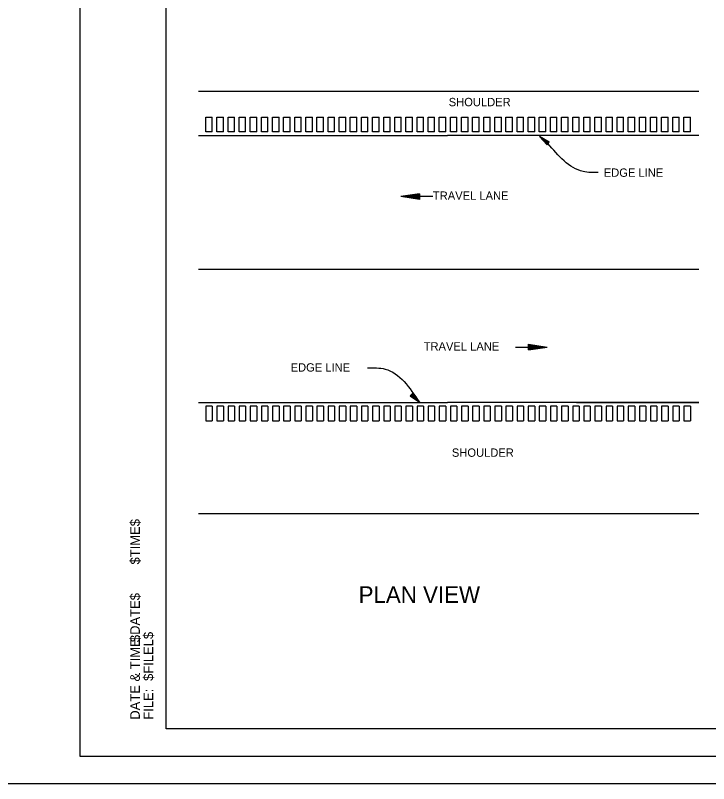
# Model space of a CAD drawing. Extents: x 3575 to 11445, y 9479 to 13278.
# Drawn here: x 7536 to 8035, y 10000 to 10553 of the extents above; entities that cross this region are included whole.
import ezdxf

# ---------------------------------------------------------------- set-up
doc = ezdxf.new("R2010")
doc.units = 0
for name, color, linetype in [('Default', 7, 'Continuous'), ('R_NoPlot', 7, 'Continuous'), ('STAMP_PRELIMINARY', 7, 'Continuous')]:
    doc.layers.add(name, color=color, linetype=linetype)

msp = doc.modelspace()

# ---------------------------------------------------------------- linework, layer by layer
at = {"layer": 'Default'}
for p, q in [((7667.92, 10498.47), (8027.8, 10498.47)), ((7673.12, 10469.13), (7673.12, 10479.77)), ((7673.12, 10479.77), (7677.8, 10479.77)), ((7677.8, 10469.13), (7677.8, 10479.77)), ((7681.12, 10469.13), (7681.12, 10479.77)), ((7681.12, 10479.77), (7685.8, 10479.77)), ((7685.8, 10469.13), (7685.8, 10479.77)), ((7689.12, 10469.13), (7689.12, 10479.77)), ((7689.12, 10479.77), (7693.8, 10479.77)), ((7693.8, 10469.13), (7693.8, 10479.77)), ((7697.12, 10469.13), (7697.12, 10479.77)), ((7697.12, 10479.77), (7701.8, 10479.77)), ((7701.8, 10469.13), (7701.8, 10479.77)), ((7705.12, 10469.13), (7705.12, 10479.77)), ((7705.12, 10479.77), (7709.8, 10479.77)), ((7709.8, 10469.13), (7709.8, 10479.77)), ((7713.12, 10469.13), (7713.12, 10479.77)), ((7713.12, 10479.77), (7717.8, 10479.77)), ((7717.8, 10469.13), (7717.8, 10479.77)), ((7721.12, 10469.13), (7721.12, 10479.77)), ((7721.12, 10479.77), (7725.8, 10479.77)), ((7725.8, 10469.13), (7725.8, 10479.77)), ((7729.12, 10469.13), (7729.12, 10479.77)), ((7729.12, 10479.77), (7733.8, 10479.77)), ((7733.8, 10469.13), (7733.8, 10479.77)), ((7737.12, 10469.13), (7737.12, 10479.77)), ((7737.12, 10479.77), (7741.8, 10479.77)), ((7741.8, 10469.13), (7741.8, 10479.77)), ((7745.12, 10469.13), (7745.12, 10479.77)), ((7745.12, 10479.77), (7749.8, 10479.77)), ((7749.8, 10469.13), (7749.8, 10479.77)), ((7753.12, 10469.13), (7753.12, 10479.77)), ((7753.12, 10479.77), (7757.8, 10479.77)), ((7757.8, 10469.13), (7757.8, 10479.77)), ((7761.12, 10469.13), (7761.12, 10479.77)), ((7761.12, 10479.77), (7765.8, 10479.77)), ((7765.8, 10469.13), (7765.8, 10479.77)), ((7769.12, 10469.13), (7769.12, 10479.77)), ((7769.12, 10479.77), (7773.8, 10479.77)), ((7773.8, 10469.13), (7773.8, 10479.77)), ((7777.12, 10469.13), (7777.12, 10479.77)), ((7777.12, 10479.77), (7781.8, 10479.77)), ((7781.8, 10469.13), (7781.8, 10479.77)), ((7785.12, 10469.13), (7785.12, 10479.77)), ((7785.12, 10479.77), (7789.8, 10479.77)), ((7789.8, 10469.13), (7789.8, 10479.77)), ((7793.12, 10469.13), (7793.12, 10479.77)), ((7793.12, 10469.13), (7793.12, 10479.77)), ((7793.12, 10479.77), (7797.8, 10479.77)), ((7797.8, 10469.13), (7797.8, 10479.77)), ((7801.12, 10469.13), (7801.12, 10479.77)), ((7801.12, 10479.77), (7805.8, 10479.77)), ((7805.8, 10469.13), (7805.8, 10479.77)), ((7809.12, 10469.13), (7809.12, 10479.77)), ((7809.12, 10479.77), (7813.8, 10479.77)), ((7813.8, 10469.13), (7813.8, 10479.77)), ((7817.12, 10469.13), (7817.12, 10479.77)), ((7817.12, 10479.77), (7821.8, 10479.77)), ((7821.8, 10469.13), (7821.8, 10479.77)), ((7825.12, 10469.13), (7825.12, 10479.77)), ((7825.12, 10479.77), (7829.8, 10479.77)), ((7829.8, 10469.13), (7829.8, 10479.77)), ((7833.12, 10469.13), (7833.12, 10479.77)), ((7833.12, 10479.77), (7837.8, 10479.77)), ((7837.8, 10469.13), (7837.8, 10479.77)), ((7841.12, 10469.13), (7841.12, 10479.77)), ((7841.12, 10479.77), (7845.8, 10479.77)), ((7845.8, 10469.13), (7845.8, 10479.77)), ((7849.12, 10469.13), (7849.12, 10479.77)), ((7849.12, 10479.77), (7853.8, 10479.77)), ((7853.8, 10469.13), (7853.8, 10479.77)), ((7857.12, 10469.13), (7857.12, 10479.77)), ((7857.12, 10479.77), (7861.8, 10479.77)), ((7861.8, 10469.13), (7861.8, 10479.77)), ((7865.12, 10469.13), (7865.12, 10479.77)), ((7865.12, 10479.77), (7869.8, 10479.77)), ((7869.8, 10469.13), (7869.8, 10479.77)), ((7873.12, 10469.13), (7873.12, 10479.77)), ((7873.12, 10479.77), (7877.8, 10479.77)), ((7877.8, 10469.13), (7877.8, 10479.77)), ((7881.12, 10469.13), (7881.12, 10479.77)), ((7881.12, 10479.77), (7885.8, 10479.77)), ((7885.8, 10469.13), (7885.8, 10479.77)), ((7889.12, 10469.13), (7889.12, 10479.77)), ((7889.12, 10479.77), (7893.8, 10479.77)), ((7893.8, 10469.13), (7893.8, 10479.77)), ((7897.12, 10469.13), (7897.12, 10479.77)), ((7897.12, 10479.77), (7901.8, 10479.77)), ((7901.8, 10469.13), (7901.8, 10479.77)), ((7905.12, 10469.13), (7905.12, 10479.77)), ((7905.12, 10479.77), (7909.8, 10479.77)), ((7909.8, 10469.13), (7909.8, 10479.77)), ((7913.12, 10469.13), (7913.12, 10479.77)), ((7913.12, 10479.77), (7917.8, 10479.77)), ((7917.8, 10469.13), (7917.8, 10479.77)), ((7921.12, 10469.13), (7921.12, 10479.77)), ((7921.12, 10479.77), (7925.8, 10479.77)), ((7925.8, 10469.13), (7925.8, 10479.77)), ((7929.12, 10469.13), (7929.12, 10479.77)), ((7929.12, 10479.77), (7933.8, 10479.77)), ((7933.8, 10469.13), (7933.8, 10479.77)), ((7937.12, 10469.13), (7937.12, 10479.77)), ((7937.12, 10479.77), (7941.8, 10479.77)), ((7941.8, 10469.13), (7941.8, 10479.77)), ((7945.12, 10469.13), (7945.12, 10479.77)), ((7945.12, 10479.77), (7949.8, 10479.77)), ((7949.8, 10469.13), (7949.8, 10479.77)), ((7953.12, 10469.13), (7953.12, 10479.77)), ((7953.12, 10479.77), (7957.8, 10479.77)), ((7957.8, 10469.13), (7957.8, 10479.77)), ((7961.12, 10469.13), (7961.12, 10479.77)), ((7961.12, 10479.77), (7965.8, 10479.77)), ((7965.8, 10469.13), (7965.8, 10479.77)), ((7969.12, 10469.13), (7969.12, 10479.77)), ((7969.12, 10479.77), (7973.8, 10479.77)), ((7973.8, 10469.13), (7973.8, 10479.77)), ((7977.12, 10469.13), (7977.12, 10479.77)), ((7977.12, 10479.77), (7981.8, 10479.77)), ((7981.8, 10469.13), (7981.8, 10479.77)), ((7985.12, 10469.13), (7985.12, 10479.77)), ((7985.12, 10479.77), (7989.8, 10479.77)), ((7989.8, 10469.13), (7989.8, 10479.77)), ((7993.12, 10469.13), (7993.12, 10479.77)), ((7993.12, 10479.77), (7997.8, 10479.77)), ((7997.8, 10469.13), (7997.8, 10479.77)), ((8001.12, 10469.13), (8001.12, 10479.77)), ((8001.12, 10479.77), (8005.8, 10479.77)), ((8005.8, 10469.13), (8005.8, 10479.77)), ((8009.12, 10469.13), (8009.12, 10479.77)), ((8009.12, 10479.77), (8013.8, 10479.77)), ((8013.8, 10469.13), (8013.8, 10479.77)), ((8017.12, 10469.13), (8017.12, 10479.77)), ((8017.12, 10479.77), (8021.8, 10479.77)), ((8021.8, 10469.13), (8021.8, 10479.77)), ((7667.92, 10466.47), (7847.02, 10466.47)), ((7677.8, 10469.13), (7673.12, 10469.13)), ((7685.8, 10469.13), (7681.12, 10469.13)), ((7693.8, 10469.13), (7689.12, 10469.13)), ((7701.8, 10469.13), (7697.12, 10469.13)), ((7709.8, 10469.13), (7705.12, 10469.13)), ((7717.8, 10469.13), (7713.12, 10469.13)), ((7725.8, 10469.13), (7721.12, 10469.13)), ((7733.8, 10469.13), (7729.12, 10469.13)), ((7741.8, 10469.13), (7737.12, 10469.13)), ((7749.8, 10469.13), (7745.12, 10469.13)), ((7757.8, 10469.13), (7753.12, 10469.13)), ((7765.8, 10469.13), (7761.12, 10469.13)), ((7773.8, 10469.13), (7769.12, 10469.13)), ((7781.8, 10469.13), (7777.12, 10469.13)), ((7789.8, 10469.13), (7785.12, 10469.13)), ((7797.8, 10469.13), (7793.12, 10469.13)), ((7805.8, 10469.13), (7801.12, 10469.13)), ((7813.8, 10469.13), (7809.12, 10469.13)), ((7821.8, 10469.13), (7817.12, 10469.13)), ((7829.8, 10469.13), (7825.12, 10469.13)), ((7837.8, 10469.13), (7833.12, 10469.13)), ((7845.8, 10469.13), (7841.12, 10469.13)), ((8027.8, 10466.47), (7847.02, 10466.47)), ((7853.8, 10469.13), (7849.12, 10469.13)), ((7861.8, 10469.13), (7857.12, 10469.13)), ((7869.8, 10469.13), (7865.12, 10469.13)), ((7877.8, 10469.13), (7873.12, 10469.13)), ((7885.8, 10469.13), (7881.12, 10469.13)), ((7893.8, 10469.13), (7889.12, 10469.13)), ((7901.8, 10469.13), (7897.12, 10469.13)), ((7909.8, 10469.13), (7905.12, 10469.13)), ((7917.8, 10469.13), (7913.12, 10469.13)), ((7918.74, 10459.91), (7913.24, 10465.85)), ((7920.24, 10461.79), (7913.24, 10465.85)), ((7918.86, 10460.07), (7914.28, 10465.01)), ((7920.12, 10461.63), (7914.28, 10465.01)), ((7919.98, 10461.47), (7915.36, 10464.17)), ((7919, 10460.23), (7915.36, 10464.17)), ((7925.8, 10469.13), (7921.12, 10469.13)), ((7933.8, 10469.13), (7929.12, 10469.13)), ((7941.8, 10469.13), (7937.12, 10469.13)), ((7949.8, 10469.13), (7945.12, 10469.13)), ((7957.8, 10469.13), (7953.12, 10469.13)), ((7965.8, 10469.13), (7961.12, 10469.13)), ((7973.8, 10469.13), (7969.12, 10469.13)), ((7981.8, 10469.13), (7977.12, 10469.13)), ((7989.8, 10469.13), (7985.12, 10469.13)), ((7997.8, 10469.13), (7993.12, 10469.13)), ((8005.8, 10469.13), (8001.12, 10469.13)), ((8013.8, 10469.13), (8009.12, 10469.13)), ((8021.8, 10469.13), (8017.12, 10469.13)), ((7919.12, 10460.39), (7916.4, 10463.33)), ((7919.86, 10461.31), (7916.4, 10463.33)), ((7919.72, 10461.15), (7917.46, 10462.47)), ((7919.24, 10460.55), (7917.46, 10462.47)), ((7919.6, 10460.99), (7918.5, 10461.65)), ((7919.36, 10460.71), (7918.5, 10461.65)), ((7918.74, 10459.91), (7920.24, 10461.79)), ((7826.94, 10424.6), (7813.5, 10422.58)), ((7836.38, 10422.58), (7813.5, 10422.58)), ((7826.94, 10420.58), (7813.5, 10422.58)), ((7826.94, 10424.26), (7815.74, 10422.58)), ((7826.94, 10420.9), (7815.74, 10422.58)), ((7826.94, 10423.94), (7818.04, 10422.58)), ((7826.94, 10421.26), (7818.04, 10422.58)), ((7826.94, 10423.58), (7820.26, 10422.58)), ((7826.94, 10421.58), (7820.26, 10422.58)), ((7826.94, 10423.22), (7822.56, 10422.58)), ((7826.94, 10421.92), (7822.56, 10422.58)), ((7826.94, 10422.92), (7824.8, 10422.58)), ((7826.94, 10422.26), (7824.8, 10422.58)), ((7826.94, 10424.6), (7826.94, 10420.58)), ((7667.92, 10370.46), (8027.8, 10370.46)), ((7905.4, 10316.26), (7918.84, 10314.28)), ((7905.4, 10312.26), (7905.4, 10316.26)), ((7905.4, 10315.94), (7916.6, 10314.28)), ((7905.4, 10315.6), (7914.3, 10314.28)), ((7905.4, 10315.26), (7912.08, 10314.28)), ((7905.4, 10314.92), (7909.78, 10314.28)), ((7905.4, 10314.6), (7907.54, 10314.28)), ((7895.96, 10314.28), (7918.84, 10314.28)), ((7905.4, 10312.26), (7918.84, 10314.28)), ((7905.4, 10313.62), (7909.78, 10314.28)), ((7905.4, 10312.92), (7914.3, 10314.28)), ((7905.4, 10312.58), (7916.6, 10314.28)), ((7905.4, 10313.26), (7912.08, 10314.28)), ((7905.4, 10313.94), (7907.54, 10314.28)), ((7821.92, 10280.96), (7820.26, 10279.24)), ((7820.26, 10279.24), (7826.84, 10274.52)), ((7820.4, 10279.38), (7825.88, 10275.46)), ((7820.54, 10279.52), (7824.88, 10276.42)), ((7820.68, 10279.66), (7823.94, 10277.34)), ((7820.82, 10279.8), (7822.96, 10278.28)), ((7820.96, 10279.96), (7822, 10279.22)), ((7821.22, 10280.22), (7822, 10279.22)), ((7821.36, 10280.36), (7822.96, 10278.28)), ((7821.5, 10280.52), (7823.94, 10277.34)), ((7821.64, 10280.66), (7824.88, 10276.42)), ((7821.78, 10280.8), (7825.88, 10275.46)), ((7821.92, 10280.96), (7826.84, 10274.52)), ((7667.92, 10274.46), (7847.02, 10274.46)), ((7677.8, 10271.8), (7673.12, 10271.8)), ((7673.12, 10271.8), (7673.12, 10261.16)), ((7677.8, 10271.8), (7677.8, 10261.16)), ((7685.8, 10271.8), (7681.12, 10271.8)), ((7681.12, 10271.8), (7681.12, 10261.16)), ((7685.8, 10271.8), (7685.8, 10261.16)), ((7693.8, 10271.8), (7689.12, 10271.8)), ((7689.12, 10271.8), (7689.12, 10261.16)), ((7693.8, 10271.8), (7693.8, 10261.16)), ((7701.8, 10271.8), (7697.12, 10271.8)), ((7697.12, 10271.8), (7697.12, 10261.16)), ((7701.8, 10271.8), (7701.8, 10261.16)), ((7709.8, 10271.8), (7705.12, 10271.8)), ((7705.12, 10271.8), (7705.12, 10261.16)), ((7709.8, 10271.8), (7709.8, 10261.16)), ((7717.8, 10271.8), (7713.12, 10271.8)), ((7713.12, 10271.8), (7713.12, 10261.16)), ((7717.8, 10271.8), (7717.8, 10261.16)), ((7725.8, 10271.8), (7721.12, 10271.8)), ((7721.12, 10271.8), (7721.12, 10261.16)), ((7725.8, 10271.8), (7725.8, 10261.16)), ((7733.8, 10271.8), (7729.12, 10271.8)), ((7729.12, 10271.8), (7729.12, 10261.16)), ((7733.8, 10271.8), (7733.8, 10261.16)), ((7741.8, 10271.8), (7737.12, 10271.8)), ((7737.12, 10271.8), (7737.12, 10261.16)), ((7741.8, 10271.8), (7741.8, 10261.16)), ((7749.8, 10271.8), (7745.12, 10271.8)), ((7745.12, 10271.8), (7745.12, 10261.16)), ((7749.8, 10271.8), (7749.8, 10261.16)), ((7757.8, 10271.8), (7753.12, 10271.8)), ((7753.12, 10271.8), (7753.12, 10261.16)), ((7757.8, 10271.8), (7757.8, 10261.16)), ((7765.8, 10271.8), (7761.12, 10271.8)), ((7761.12, 10271.8), (7761.12, 10261.16)), ((7765.8, 10271.8), (7765.8, 10261.16)), ((7773.8, 10271.8), (7769.12, 10271.8)), ((7769.12, 10271.8), (7769.12, 10261.16)), ((7773.8, 10271.8), (7773.8, 10261.16)), ((7781.8, 10271.8), (7777.12, 10271.8)), ((7777.12, 10271.8), (7777.12, 10261.16)), ((7781.8, 10271.8), (7781.8, 10261.16)), ((7789.8, 10271.8), (7785.12, 10271.8)), ((7785.12, 10271.8), (7785.12, 10261.16)), ((7789.8, 10271.8), (7789.8, 10261.16)), ((7797.8, 10271.8), (7793.12, 10271.8)), ((7793.12, 10271.8), (7793.12, 10261.16)), ((7797.8, 10271.8), (7797.8, 10261.16)), ((7805.8, 10271.8), (7801.12, 10271.8)), ((7801.12, 10271.8), (7801.12, 10261.16)), ((7805.8, 10271.8), (7805.8, 10261.16)), ((7813.8, 10271.8), (7809.12, 10271.8)), ((7809.12, 10271.8), (7809.12, 10261.16)), ((7813.8, 10271.8), (7813.8, 10261.16)), ((7821.8, 10271.8), (7817.12, 10271.8)), ((7817.12, 10271.8), (7817.12, 10261.16)), ((7821.8, 10271.8), (7821.8, 10261.16)), ((7829.8, 10271.8), (7825.12, 10271.8)), ((7825.12, 10271.8), (7825.12, 10261.16)), ((7829.8, 10271.8), (7829.8, 10261.16)), ((7837.8, 10271.8), (7833.12, 10271.8)), ((7833.12, 10271.8), (7833.12, 10261.16)), ((7837.8, 10271.8), (7837.8, 10261.16)), ((7845.8, 10271.8), (7841.12, 10271.8)), ((7841.12, 10271.8), (7841.12, 10261.16)), ((7845.8, 10271.8), (7845.8, 10261.16)), ((8027.8, 10274.46), (7847.02, 10274.46)), ((7853.8, 10271.8), (7849.12, 10271.8)), ((7849.12, 10271.8), (7849.12, 10261.16)), ((7853.8, 10271.8), (7853.8, 10261.16)), ((7861.8, 10271.8), (7857.12, 10271.8)), ((7857.12, 10271.8), (7857.12, 10261.16)), ((7861.8, 10271.8), (7861.8, 10261.16)), ((7869.8, 10271.8), (7865.12, 10271.8)), ((7865.12, 10271.8), (7865.12, 10261.16)), ((7869.8, 10271.8), (7869.8, 10261.16)), ((7877.8, 10271.8), (7873.12, 10271.8)), ((7873.12, 10271.8), (7873.12, 10261.16)), ((7877.8, 10271.8), (7877.8, 10261.16)), ((7885.8, 10271.8), (7881.12, 10271.8)), ((7881.12, 10271.8), (7881.12, 10261.16)), ((7885.8, 10271.8), (7885.8, 10261.16)), ((7893.8, 10271.8), (7889.12, 10271.8)), ((7889.12, 10271.8), (7889.12, 10261.16)), ((7893.8, 10271.8), (7893.8, 10261.16)), ((7901.8, 10271.8), (7897.12, 10271.8)), ((7897.12, 10271.8), (7897.12, 10261.16)), ((7901.8, 10271.8), (7901.8, 10261.16)), ((7909.8, 10271.8), (7905.12, 10271.8)), ((7905.12, 10271.8), (7905.12, 10261.16)), ((7909.8, 10271.8), (7909.8, 10261.16)), ((7917.8, 10271.8), (7913.12, 10271.8)), ((7913.12, 10271.8), (7913.12, 10261.16)), ((7917.8, 10271.8), (7917.8, 10261.16)), ((7925.8, 10271.8), (7921.12, 10271.8)), ((7921.12, 10271.8), (7921.12, 10261.16)), ((7925.8, 10271.8), (7925.8, 10261.16)), ((7933.8, 10271.8), (7929.12, 10271.8)), ((7929.12, 10271.8), (7929.12, 10261.16)), ((7933.8, 10271.8), (7933.8, 10261.16)), ((7941.8, 10271.8), (7937.12, 10271.8)), ((7937.12, 10271.8), (7937.12, 10261.16)), ((7939.92, 10274.46), (8027.8, 10274.46)), ((7941.8, 10271.8), (7941.8, 10261.16)), ((7949.8, 10271.8), (7945.12, 10271.8)), ((7945.12, 10271.8), (7945.12, 10261.16)), ((7949.8, 10271.8), (7949.8, 10261.16)), ((7957.8, 10271.8), (7953.12, 10271.8)), ((7953.12, 10271.8), (7953.12, 10261.16)), ((7957.8, 10271.8), (7957.8, 10261.16)), ((7965.8, 10271.8), (7961.12, 10271.8)), ((7961.12, 10271.8), (7961.12, 10261.16)), ((7965.8, 10271.8), (7965.8, 10261.16)), ((7973.8, 10271.8), (7969.12, 10271.8)), ((7969.12, 10271.8), (7969.12, 10261.16)), ((7973.8, 10271.8), (7973.8, 10261.16)), ((7981.8, 10271.8), (7977.12, 10271.8)), ((7977.12, 10271.8), (7977.12, 10261.16)), ((7981.8, 10271.8), (7981.8, 10261.16)), ((7989.8, 10271.8), (7985.12, 10271.8)), ((7985.12, 10271.8), (7985.12, 10261.16)), ((7989.8, 10271.8), (7989.8, 10261.16)), ((7997.8, 10271.8), (7993.12, 10271.8)), ((7993.12, 10271.8), (7993.12, 10261.16)), ((7997.8, 10271.8), (7997.8, 10261.16)), ((8005.8, 10271.8), (8001.12, 10271.8)), ((8001.12, 10271.8), (8001.12, 10261.16)), ((8005.8, 10271.8), (8005.8, 10261.16)), ((8013.8, 10271.8), (8009.12, 10271.8)), ((8009.12, 10271.8), (8009.12, 10261.16)), ((8013.8, 10271.8), (8013.8, 10261.16)), ((8021.8, 10271.8), (8017.12, 10271.8)), ((8017.12, 10271.8), (8017.12, 10261.16)), ((8021.8, 10271.8), (8021.8, 10261.16)), ((7673.12, 10261.16), (7677.8, 10261.16)), ((7681.12, 10261.16), (7685.8, 10261.16)), ((7689.12, 10261.16), (7693.8, 10261.16)), ((7697.12, 10261.16), (7701.8, 10261.16)), ((7705.12, 10261.16), (7709.8, 10261.16)), ((7713.12, 10261.16), (7717.8, 10261.16)), ((7721.12, 10261.16), (7725.8, 10261.16)), ((7729.12, 10261.16), (7733.8, 10261.16)), ((7737.12, 10261.16), (7741.8, 10261.16)), ((7745.12, 10261.16), (7749.8, 10261.16)), ((7753.12, 10261.16), (7757.8, 10261.16)), ((7761.12, 10261.16), (7765.8, 10261.16)), ((7769.12, 10261.16), (7773.8, 10261.16)), ((7777.12, 10261.16), (7781.8, 10261.16)), ((7785.12, 10261.16), (7789.8, 10261.16)), ((7793.12, 10261.16), (7797.8, 10261.16)), ((7801.12, 10261.16), (7805.8, 10261.16)), ((7809.12, 10261.16), (7813.8, 10261.16)), ((7817.12, 10261.16), (7821.8, 10261.16)), ((7825.12, 10261.16), (7829.8, 10261.16)), ((7833.12, 10261.16), (7837.8, 10261.16)), ((7841.12, 10261.16), (7845.8, 10261.16)), ((7849.12, 10261.16), (7853.8, 10261.16)), ((7857.12, 10261.16), (7861.8, 10261.16)), ((7865.12, 10261.16), (7869.8, 10261.16)), ((7873.12, 10261.16), (7877.8, 10261.16)), ((7881.12, 10261.16), (7885.8, 10261.16)), ((7889.12, 10261.16), (7893.8, 10261.16)), ((7897.12, 10261.16), (7901.8, 10261.16)), ((7905.12, 10261.16), (7909.8, 10261.16)), ((7913.12, 10261.16), (7917.8, 10261.16)), ((7921.12, 10261.16), (7925.8, 10261.16)), ((7929.12, 10261.16), (7933.8, 10261.16)), ((7937.12, 10261.16), (7941.8, 10261.16)), ((7945.12, 10261.16), (7949.8, 10261.16)), ((7953.12, 10261.16), (7957.8, 10261.16)), ((7961.12, 10261.16), (7965.8, 10261.16)), ((7969.12, 10261.16), (7973.8, 10261.16)), ((7977.12, 10261.16), (7981.8, 10261.16)), ((7985.12, 10261.16), (7989.8, 10261.16)), ((7993.12, 10261.16), (7997.8, 10261.16)), ((8001.12, 10261.16), (8005.8, 10261.16)), ((8009.12, 10261.16), (8013.8, 10261.16)), ((8017.12, 10261.16), (8021.8, 10261.16)), ((7667.92, 10194.46), (8027.8, 10194.46))]:
    msp.add_line(p, q, dxfattribs=at)
for points in [[(7955.52, 10439.85), (7944.68, 10440.63), (7919.2, 10460.93)], [(7789.44, 10299.28), (7802.18, 10298.4), (7826.84, 10274.52)]]:
    msp.add_spline(points, degree=3, dxfattribs=at)
at = {"layer": 'R_NoPlot'}
msp.add_lwpolyline([(7582.64, 11086.17), (9249.34, 11086.17), (9249.34, 10019.49), (7582.64, 10019.49)], close=True, dxfattribs=at)
at = {"layer": 'STAMP_PRELIMINARY'}
for p, q in [((7644.68, 10039.4), (7644.68, 11066.7)), ((9225.58, 10039.4), (7644.68, 10039.4)), ((7488.58, 10000), (9248.58, 10000))]:
    msp.add_line(p, q, dxfattribs=at)

# ---------------------------------------------------------------- texts
at = {"layer": 'Default'}
for s, height, p in [('SHOULDER', 6, (7847.92, 10487.65)), ('EDGE LINE', 6, (7959.5, 10436.83)), ('TRAVEL LANE', 6.0002, (7836.54, 10420.27)), ('TRAVEL LANE', 6.0002, (7829.9, 10311.78)), ('EDGE LINE', 6, (7734.15, 10296.61)), ('SHOULDER', 6, (7850.2, 10235.28)), ('PLAN VIEW ', 12, (7783.08, 10130.06))]:
    msp.add_text(s, height=height, dxfattribs=at).set_placement(p)
for s, height, p in [('$TIME$', 6.984, (7625.68, 10157.75)), ('$DATE$', 6.984, (7625.68, 10101.88)), ('DATE & TIME:', 6.9839, (7625.68, 10046.01)), ('$FILEL$', 6.984, (7635.28, 10073.94)), ('FILE: ', 6.984, (7635.28, 10046.01))]:
    msp.add_text(s, height=height, rotation=90, dxfattribs=at).set_placement(p)

doc.saveas('drawing.dxf')
